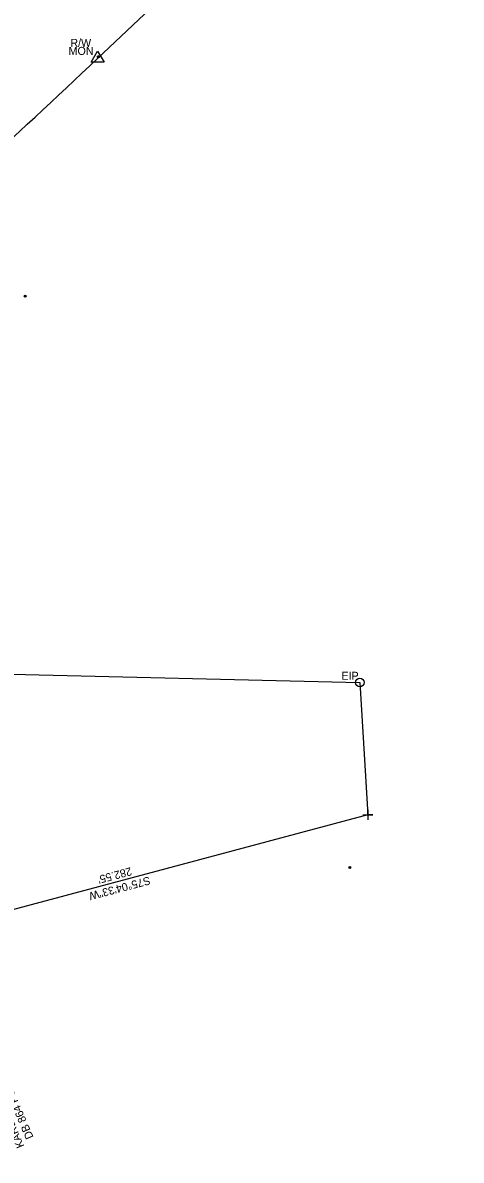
# Model space of a CAD drawing. Extents: x 1550153 to 1552579, y 809637 to 812160.
# Drawn here: x 1552156 to 1552376, y 810286 to 810857 of the extents above; entities that cross this region are included whole.
import ezdxf

# ---------------------------------------------------------------- set-up
doc = ezdxf.new("R2010")
doc.units = 0
for name, color, linetype in [('Default', 7, 'Continuous'), ('Exist DTM Crownline', 7, 'Continuous'), ('Exist Property Corner CELL', 7, 'Continuous'), ('Exist Property Iron Pin CELL', 7, 'Continuous'), ('Exist Property Iron Pin Text', 7, 'Continuous'), ('Exist Property Line', 7, 'Continuous'), ('Exist Property Line Text', 7, 'Continuous'), ('Exist Property Text', 7, 'Continuous'), ('Exist Right of Way Line', 7, 'Continuous'), ('Exist Right of Way Monument CELL', 7, 'Continuous'), ('Exist Right of Way Monument Text', 7, 'Continuous'), ('Exist Roads EOP', 7, 'Continuous')]:
    doc.layers.add(name, color=color, linetype=linetype)

# ---------------------------------------------------------------- blocks, each defined once
blk = doc.blocks.new('SurveyPointCell')
at = {"layer": 'Default'}
for p, q in [((-0.5, 0), (0.5, 0)), ((0, -0.5), (0, 0.5))]:
    blk.add_line(p, q, dxfattribs=at)
blk.add_circle((0, 0), 0.5, dxfattribs=at)

msp = doc.modelspace()

# ---------------------------------------------------------------- linework, layer by layer
at = {"layer": 'Exist DTM Crownline'}
msp.add_open_spline([(1551879.82, 810614.22), (1551884.05, 810605.39), (1551895.17, 810581.82), (1551913.83, 810543.92), (1551935.88, 810500.73), (1551958.31, 810458.41), (1551980.95, 810417.48), (1552003.45, 810377.54), (1552026.55, 810337.94), (1552050.88, 810298.4), (1552075.94, 810258.8), (1552101.84, 810219.91), (1552127.91, 810181.93), (1552154.01, 810145.21), (1552180.08, 810109.84), (1552206.53, 810074.71), (1552233.39, 810039.85), (1552251.62, 810016.53), (1552260.85, 810005.29)], degree=3, dxfattribs=at)
msp.add_open_spline([(1551879.82, 810614.22), (1551884.05, 810605.39), (1551895.17, 810581.82), (1551913.83, 810543.92), (1551935.88, 810500.73), (1551958.31, 810458.41), (1551980.95, 810417.48), (1552003.45, 810377.54), (1552026.55, 810337.94), (1552050.88, 810298.4), (1552075.94, 810258.8), (1552101.84, 810219.91), (1552127.91, 810181.93), (1552154.01, 810145.21), (1552180.08, 810109.84), (1552206.53, 810074.71), (1552233.39, 810039.85), (1552251.62, 810016.53), (1552260.85, 810005.29)], degree=3, dxfattribs=at)
at = {"layer": 'Exist Property Corner CELL'}
msp.add_line((1552329.23, 810459.15), (1552329.23, 810459.15), dxfattribs=at)
msp.add_lwpolyline([(1552326.73, 810459.15), (1552331.73, 810459.15), (1552329.23, 810459.15), (1552329.23, 810461.65), (1552329.23, 810456.65)], dxfattribs=at)
at = {"layer": 'Exist Property Iron Pin CELL'}
for radius in [2.2, 0.0707]:
    msp.add_circle((1552325.17, 810525.63), radius, dxfattribs=at)
at = {"layer": 'Exist Property Line'}
for p, q in [((1551974.86, 810534.17), (1552325.17, 810525.63)), ((1552325.17, 810525.63), (1552329.23, 810459.15)), ((1552329.23, 810459.15), (1552056.21, 810386.38))]:
    msp.add_line(p, q, dxfattribs=at)
at = {"layer": 'Exist Right of Way Line'}
msp.add_line((1552193.24, 810839.16), (1552340.77, 810978.94), dxfattribs=at)
for centre, radius, start, end in [((1544245.71, 819324.7), 11626.16, 311.427072, 313.124848), ((1554670.98, 811955.32), 3050, 212.65885, 221.20382)]:
    msp.add_arc(centre, radius, start, end, dxfattribs=at)
at = {"layer": 'Exist Right of Way Monument CELL'}
msp.add_line((1552193.24, 810839.16), (1552193.24, 810839.16), dxfattribs=at)
msp.add_lwpolyline([(1552189.99, 810837.28), (1552193.24, 810842.91), (1552196.49, 810837.28)], close=True, dxfattribs=at)
at = {"layer": 'Exist Roads EOP'}
for points in [[(1552269.13, 810011.86), (1552259.93, 810023.16), (1552240.78, 810045.4), (1552214.35, 810080.42), (1552187.88, 810115.33), (1552162.14, 810151.01), (1552135.65, 810187.58), (1552109.73, 810225.45), (1552084.16, 810264.07), (1552058.92, 810303.06), (1552035.07, 810342.61), (1552011.65, 810381.94), (1551989.05, 810421.66), (1551966.76, 810462.54), (1551944.71, 810504.82), (1551922.39, 810547.43), (1551904.23, 810585.99), (1551891.95, 810609.53), (1551888.02, 810619.12)], [(1552269.13, 810011.86), (1552259.93, 810023.16), (1552240.78, 810045.4), (1552214.35, 810080.42), (1552187.88, 810115.33), (1552162.14, 810151.01), (1552135.65, 810187.58), (1552109.73, 810225.45), (1552084.16, 810264.07), (1552058.92, 810303.06), (1552035.07, 810342.61), (1552011.65, 810381.94), (1551989.05, 810421.66), (1551966.76, 810462.54), (1551944.71, 810504.82), (1551922.39, 810547.43), (1551904.23, 810585.99), (1551891.95, 810609.53), (1551888.02, 810619.12)], [(1552253.42, 809998.9), (1552244.08, 810010.36), (1552226.02, 810034.01), (1552199.09, 810069.05), (1552172.75, 810104.35), (1552146.51, 810139.68), (1552120.18, 810176.35), (1552094.25, 810214.54), (1552068.09, 810253.47), (1552042.85, 810293.18), (1552018.16, 810332.74), (1551995.33, 810372.57), (1551972.36, 810412.53), (1551950.07, 810453.8), (1551927.46, 810496.24), (1551905.63, 810539.48), (1551886.95, 810576.34), (1551876.35, 810599.18), (1551872.14, 810607.04)], [(1552253.42, 809998.9), (1552244.08, 810010.36), (1552226.02, 810034.01), (1552199.09, 810069.05), (1552172.75, 810104.35), (1552146.51, 810139.68), (1552120.18, 810176.35), (1552094.25, 810214.54), (1552068.09, 810253.47), (1552042.85, 810293.18), (1552018.16, 810332.74), (1551995.33, 810372.57), (1551972.36, 810412.53), (1551950.07, 810453.8), (1551927.46, 810496.24), (1551905.63, 810539.48), (1551886.95, 810576.34), (1551876.35, 810599.18), (1551872.14, 810607.04)]]:
    msp.add_open_spline(points, degree=3, dxfattribs=at)

# ---------------------------------------------------------------- block references
at = {"layer": 'Default'}
for p in [(1552193.61, 810840.02), (1552193.62, 810840.03), (1552156.76, 810719.73), (1552156.77, 810719.74), (1552320.21, 810432.67), (1552320.21, 810432.66)]:
    msp.add_blockref('SurveyPointCell', p, dxfattribs=at)

# ---------------------------------------------------------------- texts
at = {"layer": 'Exist Property Iron Pin Text'}
msp.add_text('EIP', height=4.02, dxfattribs=at).set_placement((1552315.95, 810527.02))
at = {"layer": 'Exist Property Line Text'}
for s, p in [("282.55'", (1552209.83, 810432.87)), ('S75°04\'33"W', (1552219.16, 810428.25))]:
    msp.add_text(s, height=4.02, rotation=194.9242, dxfattribs=at).set_placement(p)
at = {"layer": 'Exist Property Text'}
for s, p in [('KAREN B. KILBY', (1552156.44, 810292.76)), ('DB 864 PG 723', (1552161.08, 810297.24))]:
    msp.add_text(s, height=4.02, rotation=113.1736, dxfattribs=at).set_placement(p)
at = {"layer": 'Exist Right of Way Monument Text'}
for s, p in [('R/W', (1552179.54, 810845.04)), ('MON', (1552178.65, 810841))]:
    msp.add_text(s, height=4.02, dxfattribs=at).set_placement(p)

doc.saveas('drawing.dxf')
